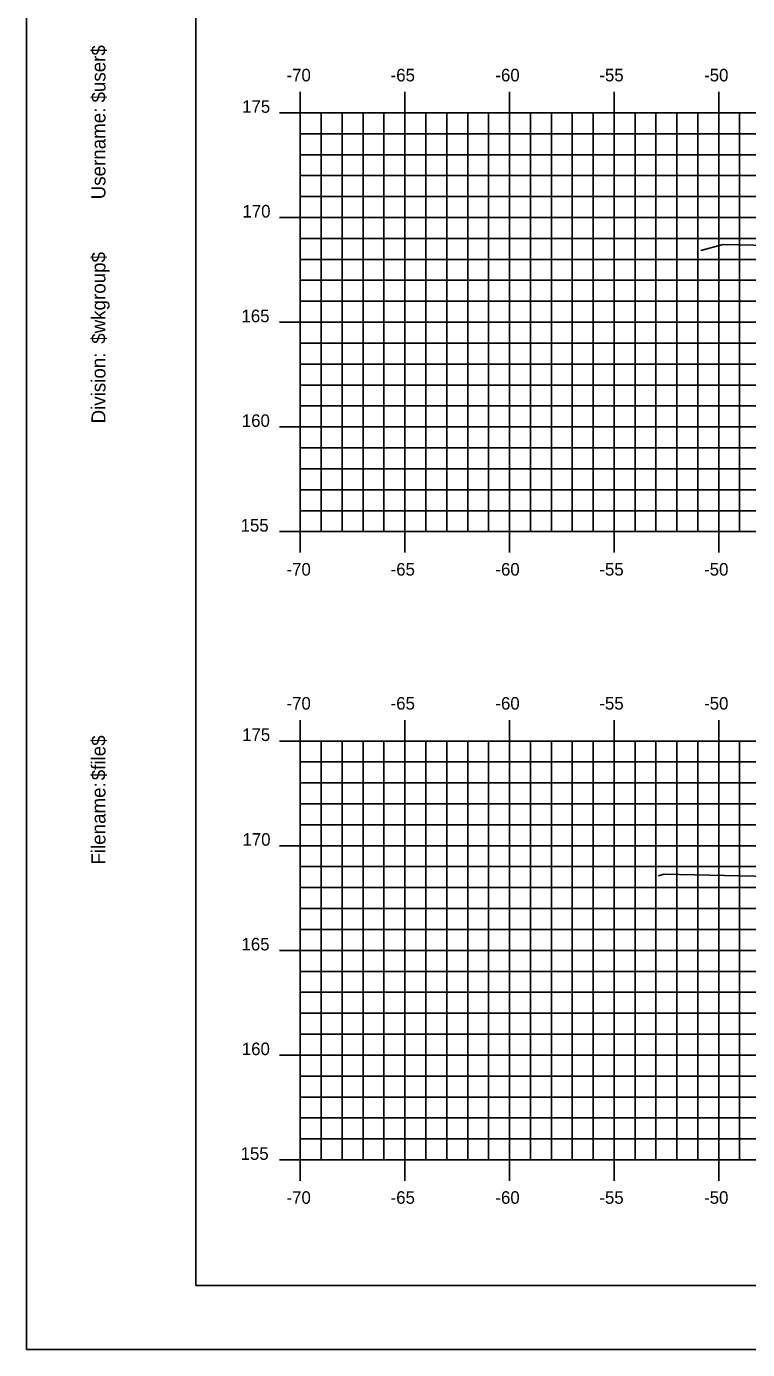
# Model space of a CAD drawing. Extents: x 1141646 to 1141816, y 608981 to 609091.
# Drawn here: x 1141645.9 to 1141680.4, y 608981.3 to 609044.5 of the extents above; entities that cross this region are included whole.
import ezdxf

# ---------------------------------------------------------------- set-up
doc = ezdxf.new("R2010")
doc.units = 0
for name, color, linetype in [('BORDER', 7, 'Continuous'), ('H_V ANNOTATION', 7, 'Continuous'), ('MAJOR', 7, 'Continuous'), ('MINOR', 7, 'Continuous'), ('PLOT BOUNDARY', 7, 'Continuous'), ('S_Roadway_Centerline', 7, 'Continuous')]:
    doc.layers.add(name, color=color, linetype=linetype)

msp = doc.modelspace()

# ---------------------------------------------------------------- linework, layer by layer
at = {"layer": 'BORDER'}
msp.add_lwpolyline([(1141654.027, 608984.335), (1141814.027, 608984.335), (1141814.027, 609089.335), (1141654.027, 609089.335)], close=True, dxfattribs=at)
at = {"layer": 'MAJOR'}
for p, q in [((1141659.027, 609041.337), (1141659.027, 609040.335)), ((1141664.027, 609041.337), (1141664.027, 609040.335)), ((1141669.027, 609041.337), (1141669.027, 609040.335)), ((1141674.027, 609041.337), (1141674.027, 609040.335)), ((1141679.027, 609041.337), (1141679.027, 609040.335)), ((1141658.025, 609040.335), (1141659.027, 609040.335)), ((1141659.027, 609040.335), (1141799.027, 609040.335)), ((1141659.027, 609020.335), (1141659.027, 609040.335)), ((1141659.027, 609020.335), (1141659.027, 609040.335)), ((1141659.027, 609040.335), (1141799.027, 609040.335)), ((1141664.027, 609020.335), (1141664.027, 609040.335)), ((1141669.027, 609020.335), (1141669.027, 609040.335)), ((1141674.027, 609020.335), (1141674.027, 609040.335)), ((1141679.027, 609020.335), (1141679.027, 609040.335)), ((1141658.025, 609035.335), (1141659.027, 609035.335)), ((1141659.027, 609035.335), (1141799.027, 609035.335)), ((1141658.025, 609030.335), (1141659.027, 609030.335)), ((1141659.027, 609030.335), (1141799.027, 609030.335)), ((1141658.025, 609025.335), (1141659.027, 609025.335)), ((1141659.027, 609025.335), (1141799.027, 609025.335)), ((1141658.025, 609020.335), (1141659.027, 609020.335)), ((1141659.027, 609020.335), (1141799.027, 609020.335)), ((1141659.027, 609020.335), (1141799.027, 609020.335)), ((1141659.027, 609019.333), (1141659.027, 609020.335)), ((1141664.027, 609019.333), (1141664.027, 609020.335)), ((1141669.027, 609019.333), (1141669.027, 609020.335)), ((1141674.027, 609019.333), (1141674.027, 609020.335)), ((1141679.027, 609019.333), (1141679.027, 609020.335)), ((1141659.027, 609011.337), (1141659.027, 609010.335)), ((1141664.027, 609011.337), (1141664.027, 609010.335)), ((1141669.027, 609011.337), (1141669.027, 609010.335)), ((1141674.027, 609011.337), (1141674.027, 609010.335)), ((1141679.027, 609011.337), (1141679.027, 609010.335)), ((1141658.025, 609010.335), (1141659.027, 609010.335)), ((1141659.027, 609010.335), (1141799.027, 609010.335)), ((1141659.027, 608990.335), (1141659.027, 609010.335)), ((1141659.027, 608990.335), (1141659.027, 609010.335)), ((1141659.027, 609010.335), (1141799.027, 609010.335)), ((1141664.027, 608990.335), (1141664.027, 609010.335)), ((1141669.027, 608990.335), (1141669.027, 609010.335)), ((1141674.027, 608990.335), (1141674.027, 609010.335)), ((1141679.027, 608990.335), (1141679.027, 609010.335)), ((1141658.025, 609005.335), (1141659.027, 609005.335)), ((1141659.027, 609005.335), (1141799.027, 609005.335)), ((1141658.025, 609000.335), (1141659.027, 609000.335)), ((1141659.027, 609000.335), (1141799.027, 609000.335)), ((1141658.025, 608995.335), (1141659.027, 608995.335)), ((1141659.027, 608995.335), (1141799.027, 608995.335)), ((1141658.025, 608990.335), (1141659.027, 608990.335)), ((1141659.027, 608990.335), (1141799.027, 608990.335)), ((1141659.027, 608990.335), (1141799.027, 608990.335)), ((1141659.027, 608989.333), (1141659.027, 608990.335)), ((1141664.027, 608989.333), (1141664.027, 608990.335)), ((1141669.027, 608989.333), (1141669.027, 608990.335)), ((1141674.027, 608989.333), (1141674.027, 608990.335)), ((1141679.027, 608989.333), (1141679.027, 608990.335))]:
    msp.add_line(p, q, dxfattribs=at)
at = {"layer": 'MINOR'}
for p, q in [((1141660.027, 609020.335), (1141660.027, 609040.335)), ((1141661.027, 609020.335), (1141661.027, 609040.335)), ((1141662.027, 609020.335), (1141662.027, 609040.335)), ((1141663.027, 609020.335), (1141663.027, 609040.335)), ((1141665.027, 609020.335), (1141665.027, 609040.335)), ((1141666.027, 609020.335), (1141666.027, 609040.335)), ((1141667.027, 609020.335), (1141667.027, 609040.335)), ((1141668.027, 609020.335), (1141668.027, 609040.335)), ((1141670.027, 609020.335), (1141670.027, 609040.335)), ((1141671.027, 609020.335), (1141671.027, 609040.335)), ((1141672.027, 609020.335), (1141672.027, 609040.335)), ((1141673.027, 609020.335), (1141673.027, 609040.335)), ((1141675.027, 609020.335), (1141675.027, 609040.335)), ((1141676.027, 609020.335), (1141676.027, 609040.335)), ((1141677.027, 609020.335), (1141677.027, 609040.335)), ((1141678.027, 609020.335), (1141678.027, 609040.335)), ((1141680.027, 609020.335), (1141680.027, 609040.335)), ((1141659.027, 609039.335), (1141799.027, 609039.335)), ((1141659.027, 609039.335), (1141660.029, 609039.335)), ((1141659.027, 609038.335), (1141799.027, 609038.335)), ((1141659.027, 609038.335), (1141660.029, 609038.335)), ((1141659.027, 609037.335), (1141799.027, 609037.335)), ((1141659.027, 609037.335), (1141660.029, 609037.335)), ((1141659.027, 609036.335), (1141799.027, 609036.335)), ((1141659.027, 609036.335), (1141660.029, 609036.335)), ((1141659.027, 609034.335), (1141799.027, 609034.335)), ((1141659.027, 609034.335), (1141660.029, 609034.335)), ((1141659.027, 609033.335), (1141799.027, 609033.335)), ((1141659.027, 609033.335), (1141660.029, 609033.335)), ((1141659.027, 609032.335), (1141799.027, 609032.335)), ((1141659.027, 609032.335), (1141660.029, 609032.335)), ((1141659.027, 609031.335), (1141799.027, 609031.335)), ((1141659.027, 609031.335), (1141660.029, 609031.335)), ((1141659.027, 609029.335), (1141799.027, 609029.335)), ((1141659.027, 609029.335), (1141660.029, 609029.335)), ((1141659.027, 609028.335), (1141799.027, 609028.335)), ((1141659.027, 609028.335), (1141660.029, 609028.335)), ((1141659.027, 609027.335), (1141799.027, 609027.335)), ((1141659.027, 609027.335), (1141660.029, 609027.335)), ((1141659.027, 609026.335), (1141799.027, 609026.335)), ((1141659.027, 609026.335), (1141660.029, 609026.335)), ((1141659.027, 609024.335), (1141799.027, 609024.335)), ((1141659.027, 609024.335), (1141660.029, 609024.335)), ((1141659.027, 609023.335), (1141799.027, 609023.335)), ((1141659.027, 609023.335), (1141660.029, 609023.335)), ((1141659.027, 609022.335), (1141799.027, 609022.335)), ((1141659.027, 609022.335), (1141660.029, 609022.335)), ((1141659.027, 609021.335), (1141799.027, 609021.335)), ((1141659.027, 609021.335), (1141660.029, 609021.335)), ((1141660.027, 608990.335), (1141660.027, 609010.335)), ((1141661.027, 608990.335), (1141661.027, 609010.335)), ((1141662.027, 608990.335), (1141662.027, 609010.335)), ((1141663.027, 608990.335), (1141663.027, 609010.335)), ((1141665.027, 608990.335), (1141665.027, 609010.335)), ((1141666.027, 608990.335), (1141666.027, 609010.335)), ((1141667.027, 608990.335), (1141667.027, 609010.335)), ((1141668.027, 608990.335), (1141668.027, 609010.335)), ((1141670.027, 608990.335), (1141670.027, 609010.335)), ((1141671.027, 608990.335), (1141671.027, 609010.335)), ((1141672.027, 608990.335), (1141672.027, 609010.335)), ((1141673.027, 608990.335), (1141673.027, 609010.335)), ((1141675.027, 608990.335), (1141675.027, 609010.335)), ((1141676.027, 608990.335), (1141676.027, 609010.335)), ((1141677.027, 608990.335), (1141677.027, 609010.335)), ((1141678.027, 608990.335), (1141678.027, 609010.335)), ((1141680.027, 608990.335), (1141680.027, 609010.335)), ((1141659.027, 609009.335), (1141799.027, 609009.335)), ((1141659.027, 609009.335), (1141660.029, 609009.335)), ((1141659.027, 609008.335), (1141799.027, 609008.335)), ((1141659.027, 609008.335), (1141660.029, 609008.335)), ((1141659.027, 609007.335), (1141799.027, 609007.335)), ((1141659.027, 609007.335), (1141660.029, 609007.335)), ((1141659.027, 609006.335), (1141799.027, 609006.335)), ((1141659.027, 609006.335), (1141660.029, 609006.335)), ((1141659.027, 609004.335), (1141799.027, 609004.335)), ((1141659.027, 609004.335), (1141660.029, 609004.335)), ((1141659.027, 609003.335), (1141799.027, 609003.335)), ((1141659.027, 609003.335), (1141660.029, 609003.335)), ((1141659.027, 609002.335), (1141799.027, 609002.335)), ((1141659.027, 609002.335), (1141660.029, 609002.335)), ((1141659.027, 609001.335), (1141799.027, 609001.335)), ((1141659.027, 609001.335), (1141660.029, 609001.335)), ((1141659.027, 608999.335), (1141799.027, 608999.335)), ((1141659.027, 608999.335), (1141660.029, 608999.335)), ((1141659.027, 608998.335), (1141799.027, 608998.335)), ((1141659.027, 608998.335), (1141660.029, 608998.335)), ((1141659.027, 608997.335), (1141799.027, 608997.335)), ((1141659.027, 608997.335), (1141660.029, 608997.335)), ((1141659.027, 608996.335), (1141799.027, 608996.335)), ((1141659.027, 608996.335), (1141660.029, 608996.335)), ((1141659.027, 608994.335), (1141799.027, 608994.335)), ((1141659.027, 608994.335), (1141660.029, 608994.335)), ((1141659.027, 608993.335), (1141799.027, 608993.335)), ((1141659.027, 608993.335), (1141660.029, 608993.335)), ((1141659.027, 608992.335), (1141799.027, 608992.335)), ((1141659.027, 608992.335), (1141660.029, 608992.335)), ((1141659.027, 608991.335), (1141799.027, 608991.335)), ((1141659.027, 608991.335), (1141660.029, 608991.335))]:
    msp.add_line(p, q, dxfattribs=at)
at = {"layer": 'PLOT BOUNDARY'}
msp.add_lwpolyline([(1141645.934, 608981.276), (1141815.934, 608981.276), (1141815.934, 609091.276), (1141645.934, 609091.276)], close=True, dxfattribs=at)
at = {"layer": 'S_Roadway_Centerline'}
for points in [[(1141678.167, 609033.767), (1141679.234, 609034.048), (1141698.041, 609033.63), (1141705.97, 609033.574), (1141711.406, 609031.629), (1141712.938, 609031.34), (1141715.436, 609031.97), (1141716.134, 609032.093), (1141717.099, 609032.186), (1141720.325, 609032.555), (1141723.008, 609032.647), (1141731.533, 609032.829), (1141740.258, 609032.604), (1141742.967, 609032.542), (1141745.916, 609032.271), (1141747.023, 609032.157), (1141748.557, 609031.535), (1141749.326, 609031.358), (1141752.88, 609032.733), (1141753.796, 609033.073), (1141762.777, 609032.834), (1141777.873, 609033.068)], [(1141676.132, 609003.905), (1141676.422, 609003.981), (1141681.475, 609003.868), (1141704.424, 609002.897), (1141713.381, 608999.604), (1141713.764, 608999.466), (1141716.715, 609000.383), (1141716.794, 609000.403), (1141716.895, 609000.414), (1141720.259, 609000.712), (1141730.384, 609000.959), (1141731.148, 609000.975), (1141741.378, 609000.622), (1141742.175, 609000.6), (1141742.437, 609000.576), (1141745.801, 609000.225), (1141745.956, 609000.162), (1141747.669, 608999.515), (1141754.519, 609002.541), (1141754.929, 609002.699), (1141757.261, 609002.735), (1141777.166, 609002.172)]]:
    msp.add_lwpolyline(points, dxfattribs=at)

# ---------------------------------------------------------------- texts
at = {"layer": 'BORDER'}
for s, p in [('$user$', (1141649.712, 609040.827)), ('Username:', (1141649.712, 609036.203)), ('$wkgroup$', (1141649.712, 609029.305)), ('Division:', (1141649.712, 609025.501)), ('$file$', (1141649.712, 609008.461)), ('Filename:', (1141649.712, 609004.433))]:
    msp.add_text(s, height=0.6696, rotation=90, dxfattribs=at).set_placement(p)
at = {"layer": 'H_V ANNOTATION'}
for s, p in [('-70', (1141658.369, 609041.835)), ('-65', (1141663.345, 609041.835)), ('-60', (1141668.353, 609041.835)), ('-55', (1141673.323, 609041.835)), ('-50', (1141678.331, 609041.835)), ('175', (1141656.248, 609040.335)), ('170', (1141656.264, 609035.335)), ('165', (1141656.216, 609030.335)), ('160', (1141656.232, 609025.335)), ('155', (1141656.173, 609020.335)), ('-70', (1141658.369, 609018.235)), ('-65', (1141663.345, 609018.235)), ('-60', (1141668.353, 609018.235)), ('-55', (1141673.323, 609018.235)), ('-50', (1141678.331, 609018.235)), ('-70', (1141658.369, 609011.835)), ('-65', (1141663.345, 609011.835)), ('-60', (1141668.353, 609011.835)), ('-55', (1141673.323, 609011.835)), ('-50', (1141678.331, 609011.835)), ('175', (1141656.248, 609010.335)), ('170', (1141656.264, 609005.335)), ('165', (1141656.216, 609000.335)), ('160', (1141656.232, 608995.335)), ('155', (1141656.173, 608990.335)), ('-70', (1141658.369, 608988.235)), ('-65', (1141663.345, 608988.235)), ('-60', (1141668.353, 608988.235)), ('-55', (1141673.323, 608988.235)), ('-50', (1141678.331, 608988.235))]:
    msp.add_text(s, height=0.6, dxfattribs=at).set_placement(p)
at = {"layer": 'MAJOR'}
for p in [(1141659.023, 609020.335), (1141659.023, 608990.335)]:
    msp.add_text('-', height=0.006, dxfattribs=at).set_placement(p)

doc.saveas('drawing.dxf')
